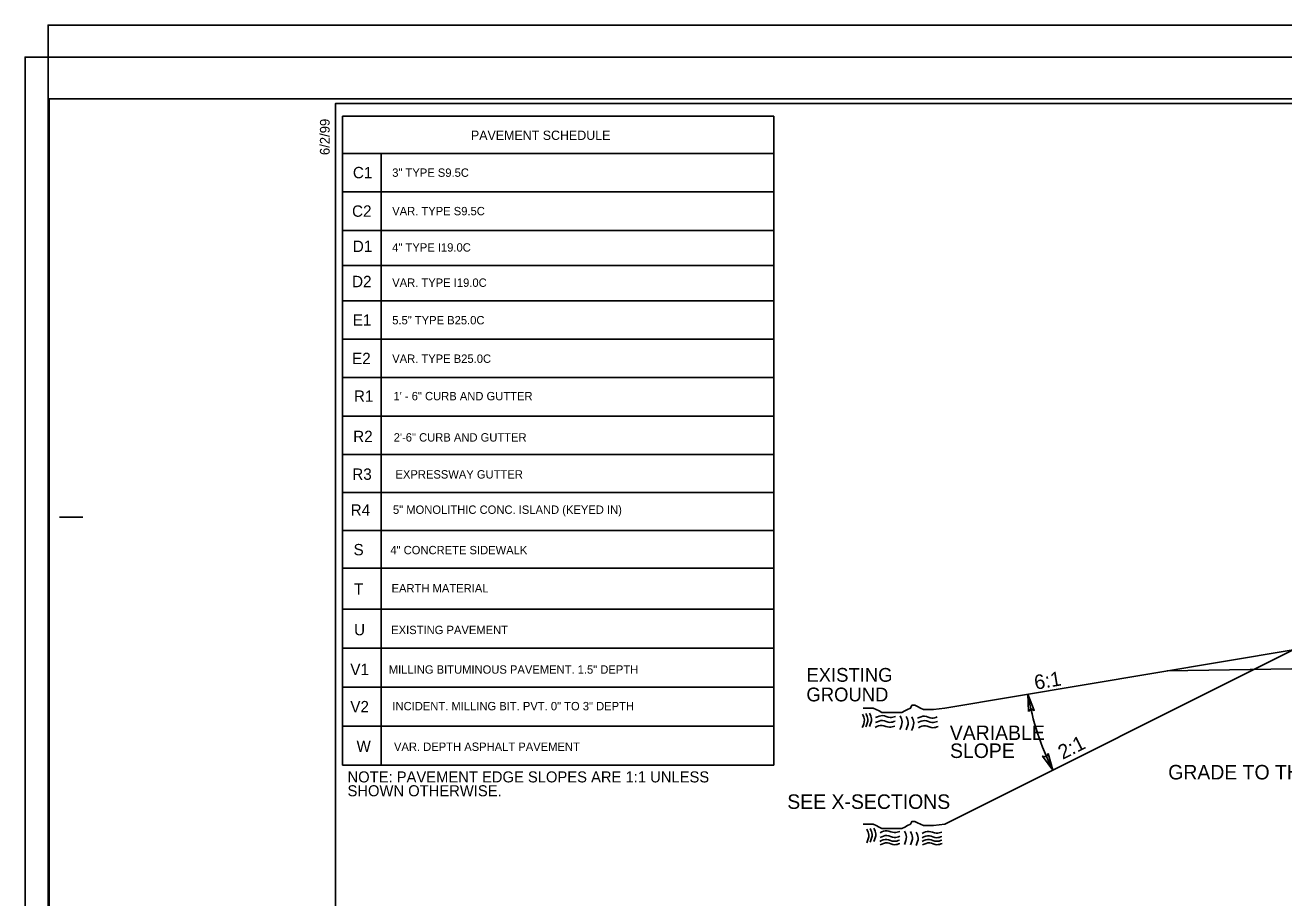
# Model space of a CAD drawing. Extents: x 2294455 to 2294795, y 719276 to 719941.
# Drawn here: x 2294454.5 to 2294590, y 719624.9 to 719718.8 of the extents above; entities that cross this region are included whole.
import ezdxf

# ---------------------------------------------------------------- set-up
doc = ezdxf.new("R2010")
doc.units = 0
for name, color, linetype in [('Default', 7, 'Continuous'), ('Old_Level_1', 7, 'Continuous'), ('Old_Level_11', 7, 'Continuous'), ('Old_Level_2', 7, 'Continuous'), ('Prop Dimension Text', 7, 'Continuous'), ('Prop Pavement Schedule Description CELL', 7, 'Continuous'), ('Sheet Plot Border Inside CELL', 7, 'Continuous'), ('Sheet Plot Border Outside CELL', 7, 'Continuous'), ('Sheet Typical CELL', 7, 'Continuous'), ('Typical Hinge Slope Arterial CELL', 7, 'Continuous')]:
    doc.layers.add(name, color=color, linetype=linetype)

msp = doc.modelspace()

# ---------------------------------------------------------------- linework, layer by layer
at = {"layer": 'Default'}
msp.add_lwpolyline([(2294454.52, 719715.33), (2294794.52, 719715.33), (2294794.52, 719495.33), (2294454.52, 719495.33)], close=True, dxfattribs=at)
at = {"layer": 'Old_Level_1'}
msp.add_line((2294598.72, 719649.65), (2294577.4, 719649.26), dxfattribs=at)
at = {"layer": 'Old_Level_11'}
for points in [[(2294562.47, 719644.9), (2294562.43, 719646.76), (2294563.1, 719645.01), (2294562.74, 719645.18)], [(2294564.6, 719640.38), (2294565.09, 719638.58), (2294564.01, 719640.11), (2294564.41, 719640.04)]]:
    msp.add_lwpolyline(points, close=True, dxfattribs=at)
at = {"layer": 'Old_Level_2'}
for points in [[(2294544.62, 719644.61), (2294544.83, 719643.99), (2294544.6, 719643.17)], [(2294544.62, 719644.61), (2294544.83, 719643.99), (2294544.6, 719643.17)], [(2294544.99, 719644.69), (2294545.2, 719644.06), (2294544.97, 719643.24)], [(2294544.99, 719644.69), (2294545.2, 719644.06), (2294544.97, 719643.24)], [(2294545.37, 719644.73), (2294545.59, 719644.1), (2294545.36, 719643.28)], [(2294545.37, 719644.73), (2294545.59, 719644.1), (2294545.36, 719643.28)], [(2294545.98, 719643.19), (2294546.73, 719643.4), (2294547.53, 719643.2), (2294548.1, 719643.33)], [(2294545.98, 719643.19), (2294546.73, 719643.4), (2294547.53, 719643.2), (2294548.1, 719643.33)], [(2294546.04, 719644.24), (2294546.79, 719644.46), (2294547.59, 719644.26), (2294548.16, 719644.38)], [(2294546.04, 719644.24), (2294546.79, 719644.46), (2294547.59, 719644.26), (2294548.16, 719644.38)], [(2294546.04, 719643.72), (2294546.79, 719643.93), (2294547.58, 719643.73), (2294548.15, 719643.86)], [(2294546.04, 719643.72), (2294546.79, 719643.93), (2294547.58, 719643.73), (2294548.15, 719643.86)], [(2294548.67, 719644.42), (2294548.88, 719643.8), (2294548.65, 719642.98)], [(2294548.67, 719644.42), (2294548.88, 719643.8), (2294548.65, 719642.98)], [(2294549.32, 719644.37), (2294549.54, 719643.75), (2294549.31, 719642.92)], [(2294549.32, 719644.37), (2294549.54, 719643.75), (2294549.31, 719642.92)], [(2294549.93, 719644.31), (2294550.14, 719643.69), (2294549.91, 719642.87)], [(2294549.93, 719644.31), (2294550.14, 719643.69), (2294549.91, 719642.87)], [(2294550.55, 719644.17), (2294551.31, 719644.39), (2294552.1, 719644.18), (2294552.67, 719644.31)], [(2294550.55, 719644.17), (2294551.31, 719644.39), (2294552.1, 719644.18), (2294552.67, 719644.31)], [(2294550.57, 719643.7), (2294551.33, 719643.92), (2294552.12, 719643.71), (2294552.69, 719643.84)], [(2294550.57, 719643.7), (2294551.33, 719643.92), (2294552.12, 719643.71), (2294552.69, 719643.84)], [(2294550.65, 719643.15), (2294551.4, 719643.37), (2294552.2, 719643.16), (2294552.77, 719643.29)], [(2294550.65, 719643.15), (2294551.4, 719643.37), (2294552.2, 719643.16), (2294552.77, 719643.29)], [(2294545.09, 719632.23), (2294545.31, 719631.61), (2294545.08, 719630.78)], [(2294545.09, 719632.23), (2294545.31, 719631.61), (2294545.08, 719630.78)], [(2294545.46, 719632.3), (2294545.67, 719631.68), (2294545.44, 719630.85)], [(2294545.46, 719632.3), (2294545.67, 719631.68), (2294545.44, 719630.85)], [(2294545.85, 719632.34), (2294546.06, 719631.72), (2294545.83, 719630.9)], [(2294545.85, 719632.34), (2294546.06, 719631.72), (2294545.83, 719630.9)], [(2294546.48, 719630.92), (2294547.24, 719631.13), (2294548.03, 719630.93), (2294548.6, 719631.06)], [(2294546.48, 719630.92), (2294547.24, 719631.13), (2294548.03, 719630.93), (2294548.6, 719631.06)], [(2294546.51, 719631.85), (2294547.26, 719632.07), (2294548.06, 719631.87), (2294548.63, 719632)], [(2294546.51, 719631.85), (2294547.26, 719632.07), (2294548.06, 719631.87), (2294548.63, 719632)], [(2294546.51, 719631.33), (2294547.26, 719631.55), (2294548.05, 719631.34), (2294548.63, 719631.47)], [(2294546.51, 719631.33), (2294547.26, 719631.55), (2294548.05, 719631.34), (2294548.63, 719631.47)], [(2294549.14, 719632.03), (2294549.35, 719631.41), (2294549.13, 719630.59)], [(2294549.14, 719632.03), (2294549.35, 719631.41), (2294549.13, 719630.59)], [(2294549.8, 719631.98), (2294550.01, 719631.36), (2294549.78, 719630.54)], [(2294549.8, 719631.98), (2294550.01, 719631.36), (2294549.78, 719630.54)], [(2294550.4, 719631.93), (2294550.62, 719631.31), (2294550.39, 719630.48)], [(2294550.4, 719631.93), (2294550.62, 719631.31), (2294550.39, 719630.48)], [(2294551.03, 719631.78), (2294551.78, 719632), (2294552.57, 719631.8), (2294553.15, 719631.92)], [(2294551.03, 719631.78), (2294551.78, 719632), (2294552.57, 719631.8), (2294553.15, 719631.92)], [(2294551.05, 719631.31), (2294551.8, 719631.53), (2294552.59, 719631.32), (2294553.17, 719631.45)], [(2294551.05, 719631.31), (2294551.8, 719631.53), (2294552.59, 719631.32), (2294553.17, 719631.45)], [(2294551.05, 719630.92), (2294551.8, 719631.13), (2294552.59, 719630.93), (2294553.17, 719631.06)], [(2294551.05, 719630.92), (2294551.8, 719631.13), (2294552.59, 719630.93), (2294553.17, 719631.06)], [(2294546.52, 719630.55), (2294547.28, 719630.77), (2294548.07, 719630.57), (2294548.65, 719630.7)], [(2294551.09, 719630.55), (2294551.84, 719630.77), (2294552.64, 719630.57), (2294553.21, 719630.7)]]:
    msp.add_spline(points, degree=3, dxfattribs=at)
at = {"layer": 'Prop Pavement Schedule Description CELL'}
for p, q in [((2294535.07, 719708.96), (2294488.68, 719708.96)), ((2294488.68, 719639.13), (2294488.68, 719708.96)), ((2294535.07, 719708.96), (2294535.07, 719639.13)), ((2294535.07, 719704.96), (2294488.68, 719704.96)), ((2294492.82, 719639.13), (2294492.82, 719704.96)), ((2294535.07, 719700.82), (2294488.68, 719700.82)), ((2294530.45, 719696.68), (2294488.68, 719696.68)), ((2294535.07, 719696.68), (2294488.68, 719696.68)), ((2294535.07, 719692.89), (2294488.68, 719692.89)), ((2294530.45, 719689.1), (2294488.68, 719689.1)), ((2294535.07, 719689.1), (2294488.68, 719689.1)), ((2294530.45, 719684.96), (2294488.68, 719684.96)), ((2294535.07, 719684.96), (2294488.68, 719684.96)), ((2294530.45, 719680.83), (2294488.68, 719680.83)), ((2294535.07, 719680.83), (2294488.68, 719680.83)), ((2294535.07, 719680.83), (2294488.68, 719680.83)), ((2294535.07, 719676.69), (2294488.68, 719676.69)), ((2294530.45, 719672.54), (2294488.68, 719672.54)), ((2294535.07, 719672.54), (2294488.68, 719672.54)), ((2294535.07, 719668.46), (2294488.68, 719668.46)), ((2294535.07, 719664.39), (2294488.68, 719664.39)), ((2294535.07, 719660.31), (2294488.68, 719660.31)), ((2294535.07, 719655.93), (2294488.68, 719655.93)), ((2294530.45, 719651.73), (2294488.68, 719651.73)), ((2294535.07, 719651.73), (2294492.82, 719651.73)), ((2294535.07, 719647.53), (2294488.68, 719647.53)), ((2294535.07, 719643.33), (2294488.68, 719643.33)), ((2294535.07, 719639.13), (2294488.68, 719639.13))]:
    msp.add_line(p, q, dxfattribs=at)
at = {"layer": 'Sheet Plot Border Inside CELL'}
msp.add_lwpolyline([(2294790.42, 719710.84), (2294457.12, 719710.84), (2294457.12, 719499.82), (2294790.42, 719499.82)], close=True, dxfattribs=at)
at = {"layer": 'Sheet Plot Border Outside CELL'}
for points in [[(2294793.79, 719718.76), (2294456.99, 719718.76), (2294456.99, 719498.76), (2294793.79, 719498.76)], [(2294794.52, 719715.33), (2294454.52, 719715.33), (2294454.52, 719495.33), (2294794.52, 719495.33)]]:
    msp.add_lwpolyline(points, close=True, dxfattribs=at)
at = {"layer": 'Sheet Typical CELL'}
msp.add_line((2294458.22, 719665.83), (2294460.72, 719665.83), dxfattribs=at)
msp.add_lwpolyline([(2294787.92, 719710.33), (2294487.92, 719710.33), (2294487.92, 719500.33), (2294787.92, 719500.33)], close=True, dxfattribs=at)
at = {"layer": 'Typical Hinge Slope Arterial CELL'}
for p, q in [((2294553.49, 719632.78), (2294590.98, 719651.52)), ((2294575.98, 719649.02), (2294590.98, 719651.52)), ((2294553.49, 719645.27), (2294575.98, 719649.02))]:
    msp.add_line(p, q, dxfattribs=at)
for points in [[(2294553.49, 719645.27), (2294552.26, 719645.12), (2294551.95, 719645.12), (2294551.49, 719645.12), (2294551.18, 719645.12), (2294550.87, 719645.27), (2294550.56, 719645.43), (2294550.25, 719645.58), (2294549.95, 719645.58), (2294549.79, 719645.27), (2294549.48, 719645.12), (2294549.18, 719644.97), (2294548.87, 719644.81), (2294548.56, 719644.81), (2294548.25, 719644.81), (2294547.94, 719644.81), (2294547.64, 719644.81), (2294547.33, 719644.81), (2294547.02, 719644.81), (2294546.71, 719644.81), (2294546.4, 719644.97), (2294546.1, 719645.12), (2294545.79, 719645.27), (2294545.33, 719645.27), (2294545.02, 719645.27), (2294544.71, 719645.27)], [(2294553.49, 719632.78), (2294552.26, 719632.62), (2294551.95, 719632.62), (2294551.49, 719632.62), (2294551.18, 719632.62), (2294550.87, 719632.78), (2294550.56, 719632.93), (2294550.25, 719633.08), (2294549.95, 719633.08), (2294549.79, 719632.78), (2294549.48, 719632.62), (2294549.18, 719632.47), (2294548.87, 719632.31), (2294548.56, 719632.31), (2294548.25, 719632.31), (2294547.94, 719632.31), (2294547.64, 719632.31), (2294547.33, 719632.31), (2294547.02, 719632.31), (2294546.71, 719632.31), (2294546.4, 719632.47), (2294546.1, 719632.62), (2294545.79, 719632.78), (2294545.33, 719632.78), (2294545.02, 719632.78), (2294544.71, 719632.78)]]:
    msp.add_lwpolyline(points, dxfattribs=at)
msp.add_arc((2294590.98, 719651.52), 28.94, 189.4624, 206.5651, dxfattribs=at)

# ---------------------------------------------------------------- texts
at = {"layer": 'Old_Level_1'}
for s, height, rotation, p in [('EXISTING', 1.484, 360, (2294538.59, 719648.1)), ('6:1', 1.562, 9.4623, (2294563.24, 719647.24)), ('GROUND', 1.484, 360, (2294538.59, 719645.99)), ('2:1', 1.562, 26.5651, (2294566.16, 719639.69)), ('SEE X-SECTIONS', 1.5625, 360, (2294536.53, 719634.42))]:
    msp.add_text(s, height=height, rotation=rotation, dxfattribs=at).set_placement(p)
at = {"layer": 'Old_Level_11'}
msp.add_text('GRADE TO THIS LINE', height=1.5625, rotation=0, dxfattribs=at).set_placement((2294577.52, 719637.59))
at = {"layer": 'Prop Dimension Text'}
for s, p in [('NOTE: PAVEMENT EDGE SLOPES ARE 1:1 UNLESS ', (2294489.21, 719637.27)), ('SHOWN OTHERWISE.', (2294489.21, 719635.78))]:
    msp.add_text(s, height=1.1875, dxfattribs=at).set_placement(p)
at = {"layer": 'Prop Pavement Schedule Description CELL'}
for s, height, p in [('C1', 1.225, (2294489.79, 719702.28)), ('3" TYPE S9.5C', 0.9, (2294494.02, 719702.44)), ('C2', 1.225, (2294489.7, 719698.14)), ('VAR. TYPE S9.5C', 0.9, (2294494.02, 719698.3)), ('D1', 1.225, (2294489.78, 719694.35)), ('4" TYPE I19.0C', 0.9, (2294494.02, 719694.39)), ('D2', 1.225, (2294489.7, 719690.56)), ('VAR. TYPE I19.0C', 0.9, (2294494.02, 719690.6)), ('E1', 1.225, (2294489.78, 719686.42)), ('5.5" TYPE B25.0C', 0.9, (2294494.02, 719686.56)), ('E2', 1.225, (2294489.7, 719682.28)), ('VAR. TYPE B25.0C', 0.9, (2294494.02, 719682.42)), ('R1', 1.225, (2294489.9, 719678.23)), ('1\' - 6" CURB AND GUTTER', 0.9, (2294494.15, 719678.39)), ('R2', 1.225, (2294489.82, 719673.89)), ('2\'-6" CURB AND GUTTER', 0.9, (2294494.18, 719673.95)), ('R3', 1.225, (2294489.72, 719669.83)), ('EXPRESSWAY GUTTER', 0.9, (2294494.37, 719669.97)), ('R4', 1.225, (2294489.55, 719665.97)), ('5" MONOLITHIC CONC. ISLAND (KEYED IN)', 0.9, (2294494.1, 719666.17)), ('S', 1.22, (2294489.86, 719661.71)), ('4" CONCRETE SIDEWALK', 0.9, (2294493.82, 719661.82)), ('T', 1.22, (2294489.92, 719657.48)), ('EARTH MATERIAL', 0.9, (2294493.95, 719657.71)), ('U', 1.22, (2294489.92, 719653.1)), ('EXISTING PAVEMENT', 0.9, (2294493.91, 719653.23)), ('V1', 1.225, (2294489.51, 719648.82)), ('MILLING BITUMINOUS PAVEMENT. 1.5" DEPTH', 0.9, (2294493.65, 719648.97)), ('V2', 1.225, (2294489.51, 719644.81)), ('INCIDENT. MILLING BIT. PVT. 0" TO 3" DEPTH', 0.9, (2294494.04, 719645.03)), ('W', 1.22, (2294490.18, 719640.56)), ('VAR. DEPTH ASPHALT PAVEMENT', 0.9, (2294494.21, 719640.66))]:
    msp.add_text(s, height=height, dxfattribs=at).set_placement(p)
at = {"layer": 'Sheet Typical CELL'}
for s, height, rotation, p in [('6/2/99', 1.05, 90, (2294487.29, 719704.78)), ('PAVEMENT SCHEDULE', 1, 360, (2294502.49, 719706.41))]:
    msp.add_text(s, height=height, rotation=rotation, dxfattribs=at).set_placement(p)
at = {"layer": 'Typical Hinge Slope Arterial CELL'}
for s, p in [('VARIABLE ', (2294554.02, 719641.83)), ('SLOPE', (2294554.04, 719639.9))]:
    msp.add_text(s, height=1.562, dxfattribs=at).set_placement(p)

doc.saveas('drawing.dxf')
